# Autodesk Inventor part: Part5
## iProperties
Shininess: 77.0
Length Units: 11269
Angle Units: 11279
Time Units: 11290
Mass Units: 11283
Length Display Precision: 3
Angle Display Precision: 2
Created: 2002-01
Part Number: Part5
Document SubType Name: Modeling
Designer: ***
Density: 1 g/cm^3
Density: 0.0
Volumn: 0.0
Area: 0.0
PropertySet Name: Model Information
Control State: 0
Master: False
Checked Out: False
Author: ***
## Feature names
1. Extrusion1
2. Extrusion2
3. Hole1
